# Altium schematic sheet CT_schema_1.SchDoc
size 510 x 258 mm
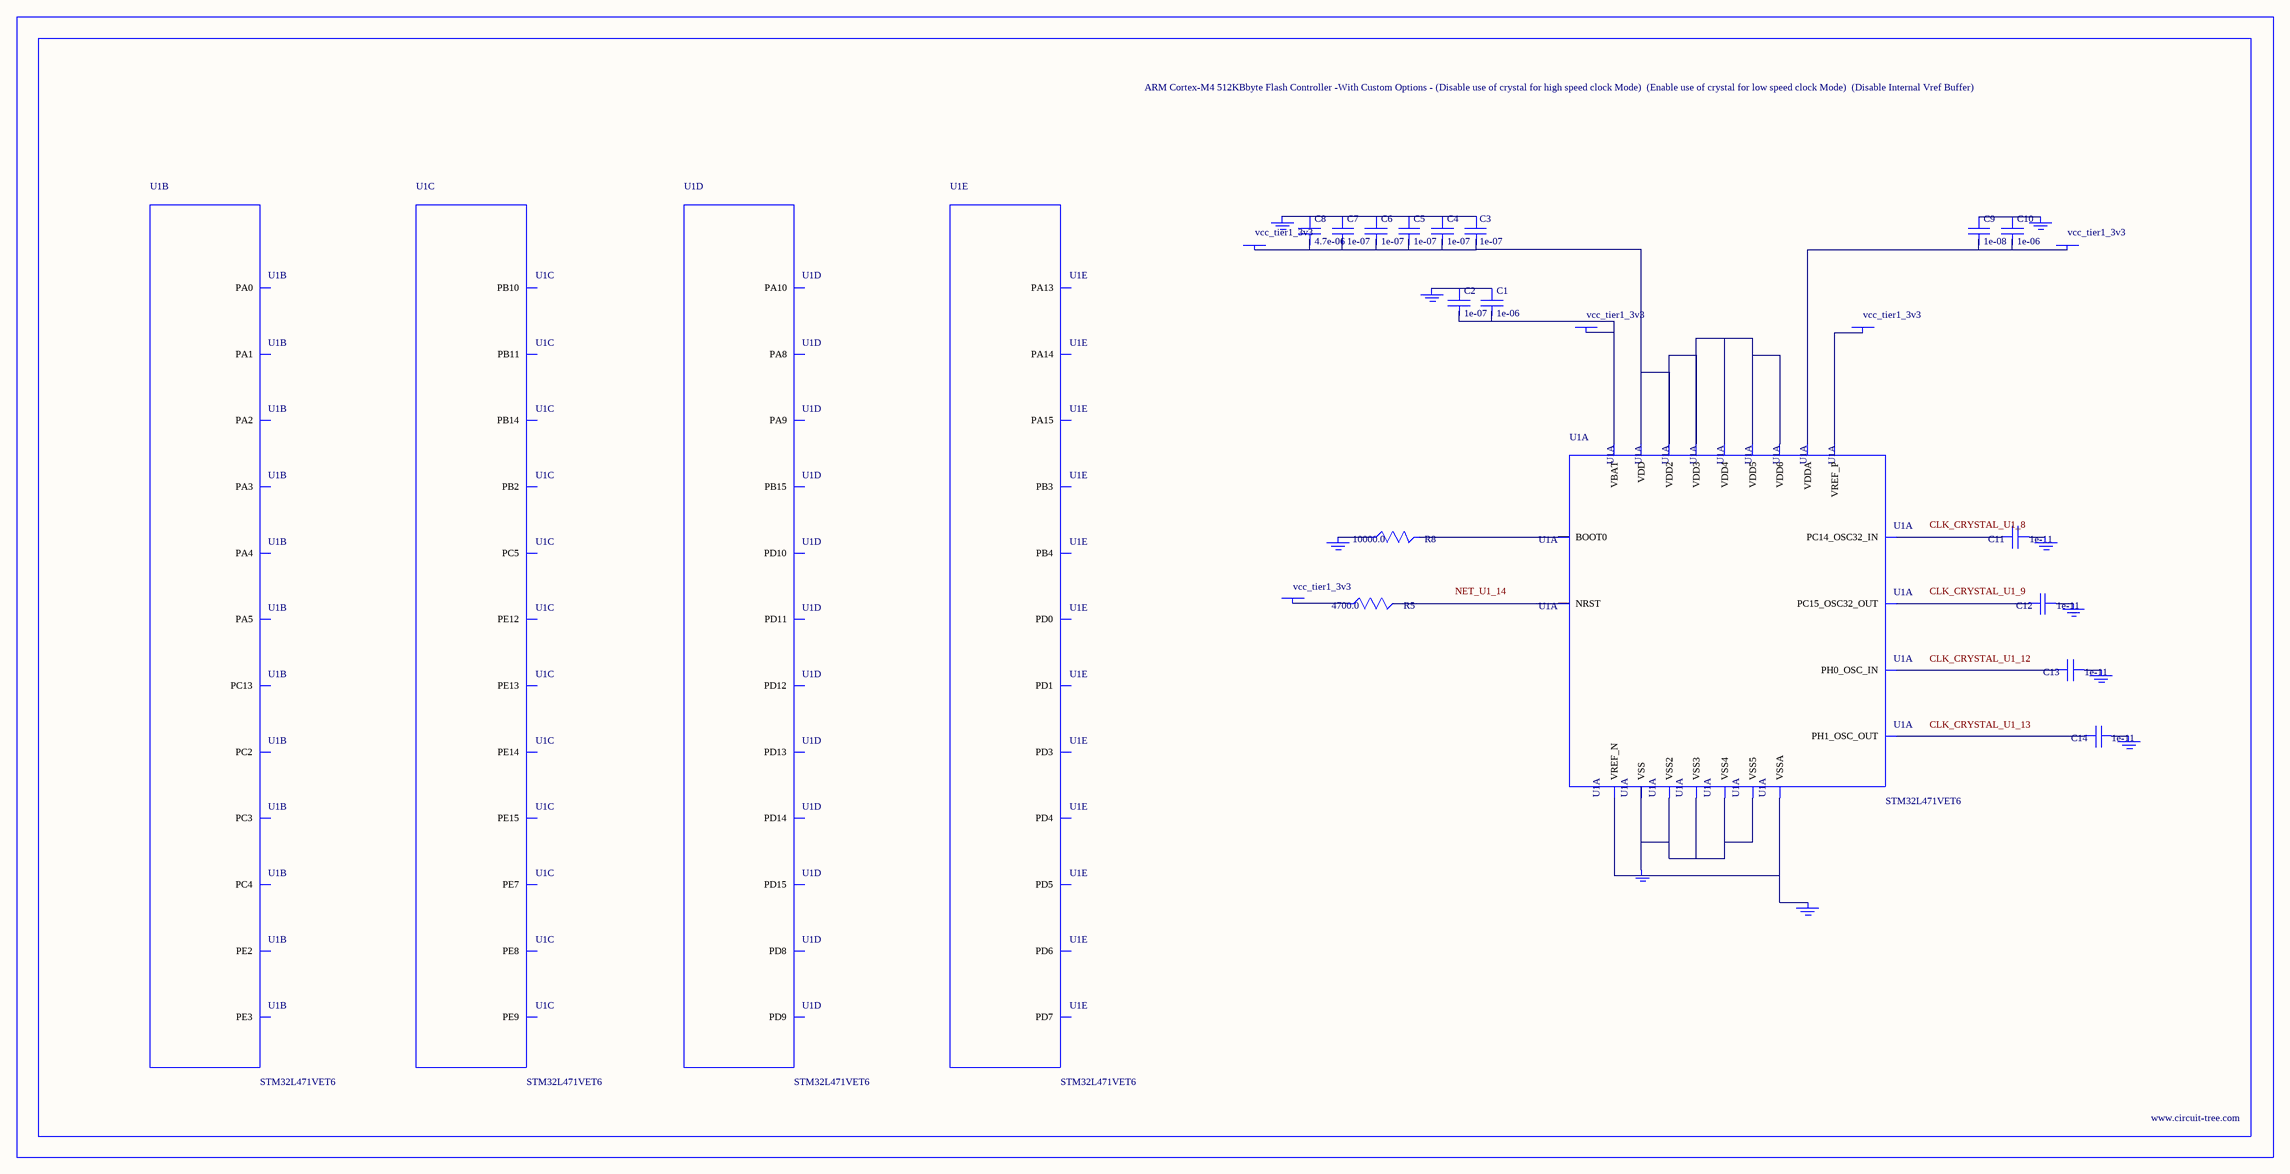
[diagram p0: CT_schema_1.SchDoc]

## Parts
BORDER0  (no value)
C1  1e-06  [C0603]
C2  1e-07  [C0603]
C3  1e-07  [C0603]
C4  1e-07  [C0603]
C5  1e-07  [C0603]
C6  1e-07  [C0603]
C7  1e-07  [C0603]
C8  4.7e-06  [C0603]
C9  1e-08  [C0603]
C10  1e-06  [C0603]
C11  1e-11  [C0402]
C12  1e-11  [C0402]
C13  1e-11  [C0402]
C14  1e-11  [C0402]
GND_INSTANCE_0_0  (no value)
GND_INSTANCE_0_1  (no value)
GND_INSTANCE_0_2  (no value)
GND_INSTANCE_0_3  (no value)
GND_INSTANCE_0_4  (no value)
GND_INSTANCE_0_5  (no value)
GND_INSTANCE_0_6  (no value)
GND_INSTANCE_0_7  (no value)
GND_INSTANCE_0_8  (no value)
GND_INSTANCE_0_9  (no value)
POWER_INSTANCE_0_0  vcc_tier1_3v3
POWER_INSTANCE_0_1  vcc_tier1_3v3
POWER_INSTANCE_0_2  vcc_tier1_3v3
POWER_INSTANCE_0_3  vcc_tier1_3v3
POWER_INSTANCE_0_4  vcc_tier1_3v3
R5  4700.0  [R0603]
R8  10000.0  [R0603]
U1  STM32L471VET6  [LQFP100]  (parts A,B,C,D,E of 11)

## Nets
NetC1_1: C1.1 C2.1 GND_INSTANCE_0_0.0(GND)
NetC1_2: C1.2 C2.2 POWER_INSTANCE_0_0.0(PWR) U1.6(VBAT)
NetC3_1: C3.1 C4.1 C5.1 C6.1 C7.1 C8.1 GND_INSTANCE_0_3.0(GND)
NetC3_2: C3.2 C4.2 C5.2 C6.2 C7.2 C8.2 POWER_INSTANCE_0_1.0(PWR) U1.11(VDD) U1.28(VDD2) U1.50(VDD3) U1.73(VDD4) U1.75(VDD5) U1.100(VDD6)
NetC9_1: C9.1 C10.1 GND_INSTANCE_0_7.0(GND)
NetC9_2: C9.2 C10.2 POWER_INSTANCE_0_3.0(PWR) U1.22(VDDA)
NetC11_1: C11.1 GND_INSTANCE_0_1.0(GND)
NetC11_2: C11.2 U1.8(PC14_OSC32_IN)
NetC12_1: C12.1 GND_INSTANCE_0_2.0(GND)
NetC12_2: C12.2 U1.9(PC15_OSC32_OUT)
NetC13_1: C13.1 GND_INSTANCE_0_4.0(GND)
NetC13_2: C13.2 U1.12(PH0_OSC_IN)
NetC14_1: C14.1 GND_INSTANCE_0_5.0(GND)
NetC14_2: C14.2 U1.13(PH1_OSC_OUT)
NetGND_INSTANCE_0_6_0: GND_INSTANCE_0_6.0(GND) U1.19(VSSA) U1.20(VREF_N)
NetGND_INSTANCE_0_8_0: GND_INSTANCE_0_8.0(GND) R8.1
NetGND_INSTANCE_0_9_0: GND_INSTANCE_0_9.0(GND) U1.10(VSS) U1.27(VSS2) U1.49(VSS3) U1.74(VSS4) U1.99(VSS5)
NetPOWER_INSTANCE_0_2_0: POWER_INSTANCE_0_2.0(PWR) U1.21(VREF_P)
NetPOWER_INSTANCE_0_4_0: POWER_INSTANCE_0_4.0(PWR) R5.1
NetR5_2: R5.2 U1.14(NRST)
NetR8_2: R8.2 U1.94(BOOT0)

Not connected (* = marked no-connect by the designer): U1 1(PE2) 2(PE3) 7(PC13) 17(PC2) 18(PC3) 23(PA0) 24(PA1) 25(PA2) 26(PA3) 29(PA4) 30(PA5) 33(PC4) 34(PC5) 37(PB2) 38(PE7) 39(PE8) 40(PE9) 43(PE12) 44(PE13) 45(PE14) 46(PE15) 47(PB10) 48(PB11) 53(PB14) 54(PB15) 55(PD8) 56(PD9) 57(PD10) 58(PD11) 59(PD12) 60(PD13) 61(PD14) 62(PD15) 67(PA8) 68(PA9) 69(PA10) 72(PA13) 76(PA14) 77(PA15) 81(PD0) 82(PD1) 84(PD3) 85(PD4) 86(PD5) 87(PD6) 88(PD7) 89(PB3) 90(PB4)

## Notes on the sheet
- Labels drawn without touching a wire or pin: CLK_CRYSTAL_U1_8, CLK_CRYSTAL_U1_9, CLK_CRYSTAL_U1_12, CLK_CRYSTAL_U1_13, NET_U1_14

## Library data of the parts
BORDER0 = BORDER_PAGE0
C1 C10 = C0603C105K3RACTU
C2-C7 = 06035C104K4Z2A
C8 = GRM188R6YA475KE15D
C9 = 06035C103K4Z2A
C11-C14 = C0402C100K3GACTU
GND_INSTANCE_0_0-GND_INSTANCE_0_9 = GND
POWER_INSTANCE_0_0-POWER_INSTANCE_0_4 = PWR
R5 = RC0603JR-074K7L
R8 = RC0603JR-0710KL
